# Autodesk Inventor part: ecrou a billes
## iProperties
Shininess: 20.0
Angle Display Precision: 2
Document Length Units: 11269
Document Angle Units: 11279
Document Time Units: 11290
Document Mass Units: 11283
Document Length Units Precision: 3
Document Angle Units Precision: 2
Compacted: True
Created: 2002-04
Part Number: ecrou a billes
Material: Par défaut
Document SubType Name: Modélisation
Designer: thchene
Density: 0.0
Volumn: 0.0
Area: 0.0
PropertySet Name: Model Information
Control State: 0
Master: False
Checked Out: False
Author: thchene
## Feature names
1. Révolution1 [Revolution]
2. Chanfrein1 [Chamfer]
3. Révolution2 [Revolution]
4. Congé1 [Fillet]
5. Chanfrein2 [Chamfer]
6. Symétrie1 [Mirror]
7. Chanfrein3 [Chamfer]
